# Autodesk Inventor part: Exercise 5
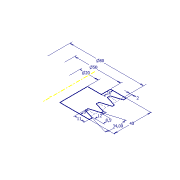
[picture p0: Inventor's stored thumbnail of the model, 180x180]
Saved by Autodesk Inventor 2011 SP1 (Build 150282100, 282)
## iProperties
Created: 2011-01
Part Number: Exercise 5
Document SubType Name: Modeling
Designer: SERGIO
Density: 1 g/cm^3
Material: Default
Author: SERGIO
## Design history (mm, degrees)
sketch "Sketch1"
  geometry: L1 (40, 12.25)-(40, 3.75); L2 (42, 12.861)-(31, 9.498); L3 (31, 9.498)-(31, 6.502); L4 (31, 6.502)-(42, 3.139); L5 (31, 8)-(40, 8); L6 (25, 40)-(42, 40); L7 (42, 0)-(10, 0); L8 (0, 48)-(0, -8) reference; L9 (25, 40)-(25, 30); L10 (25, 30)-(10, 30); L11 (10, 30)-(10, 0); L12 (40, 24.25)-(40, 15.75); L13 (31, 21.498)-(31, 18.502); L14 (31, 18.502)-(42, 15.139); L15 (42, 24.861)-(31, 21.498); L16 (31, 20)-(40, 20); L17 (40, 36.25)-(40, 27.75); L18 (31, 33.498)-(31, 30.502); L19 (31, 30.502)-(42, 27.139); L20 (42, 36.861)-(31, 33.498); L21 (31, 32)-(40, 32); L22 (42, 40)-(42, 36.861); L23 (42, 27.139)-(42, 24.861); L24 (42, 15.139)-(42, 12.861); L25 (42, 3.139)-(42, 0); 1 further point
  constraints: 48 end point, 6 point on line, 5 perpendicular, 3 collinear, 2 midpoint, 2 vertical alignment, 1 horizontal alignment, 1 vertical, 26 other
  dimensions: "d2" = 8.5 distance of L1.start L1.end; "d3" = 34 deg angle of L2 L4; "d5" = 40 distance between parallel lines of L7 L6; "d8" = 8 distance between parallel lines of L7 L5; "d33" = 11 horizontal distance of L7.start L3.end; "d36" = 50 diameter of L9 L8; "d37" = 20 diameter of L11 L8; "d38" = 10 distance between parallel lines of L6 L10; "d42" = 12 distance of L1.end L12.end; "d48" = 80 diameter of L17 L8; "d49" = 2 distance between parallel lines of L22 L17
body "Solid4"
